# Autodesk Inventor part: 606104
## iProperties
Category: PARTsolutions
Created: 2007-09
Part Number: 606104
Catalog Web Link: www.cadenas.de
Description: Nut inch - Destaco - Accessories
Document SubType Name: Modeling
Designer: PARTsolutions
Material: 1.0037 St 37-2
NB: 606104
NN: Nut inch
NT: Destaco - Accessories
NBSYN: $PN.
LINA: 606104
PN: 606104
H: 0.250
W: 1.000
PNKDM1: 0.7500
PNKDM2: 0.6820
MD: 3/4-16
NUTSIZE: 0
KT: DUMMY
PSOL_IDENT_0: {\\partserver001.servicenet\dplatte\cadenas\23d-libs\destaco\industries\manual_clamps\accessories\nu
PSOL_IDENT_1: t_inch.prj},148 {VTYP=3D},{NB=606104},{LINA=606104},{NN=Nut inch},{DATE=30.07.2007 07:21:59},{GEOMDA
PSOL_IDENT_2: TE=30.07.2007},{VERSION=},{LINEID=140},{LINESUBID=-1},{WBVAR=}  {NB=606104},{LINA=606104},{KT=DUMMY}
PSOL_IDENT_3: ,{PN=606104},{H=0.250},{W=1.000},{PNKDM1=0.7500},{PNKDM2=0.6820},{MD=3/4-16},{NUTSIZE=0}
Title: 606104
Author: Cadenas PARTsolutions
Comments: Destaco - Accessories
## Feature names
1. Revolution1
2. Extrusion1
3. Bohrung1 [Hole]
